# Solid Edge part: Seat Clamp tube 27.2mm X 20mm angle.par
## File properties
Last saved by: morva
Revision: 77
Accuracy: 0.990
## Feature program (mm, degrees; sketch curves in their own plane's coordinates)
sketch for "unnamed Protrusion 1" plane through (0.22, -6.8575, -2.251) normal (0, -1, 0) x-axis (0.94412, 0, 0.329602)
  line (-11.7005, 1.9664) -> (-10.7493, 1.6343)
  line (-10.7493, 1.6343) -> (-8.844, 0.9691)
  line (-9.4309, 5.4108) -> (-7.5256, 4.7456)
  line (-9.4309, 5.4108) -> (-10.3821, 5.7429)
extrude "unnamed Protrusion 1" add to key point along -normal
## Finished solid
Body 1: solid body, 6 faces, 12 edges, 8 vertices.
  Faces by surface: plane 4, cylinder 2
  Edges by curve: line 8, circle 4
Body 2: sheet body, 62 faces, 134 edges, 72 vertices.
  Faces by surface: cylinder 28, torus 20, plane 10, blend 4
  Edges by curve: circle 76, line 50, ellipse 8
Body 3: sheet body, 46 faces, 112 edges, 64 vertices.
  Faces by surface: cylinder 20, plane 14, torus 12
  Edges by curve: circle 50, line 44, intersection 12, ellipse 6
Body 4: sheet body, 19 faces, 49 edges, 28 vertices.
  Faces by surface: torus 10, cylinder 5, blend 4
  Edges by curve: circle 30, intersection 14, line 4, spline 1
Body 5: sheet body, 2 faces, 7 edges, 5 vertices.
  Faces by surface: spline 2
  Edges by curve: intersection 2, line 2, spline 2, curve on surface 1
Body 6: sheet body, 11 faces, 41 edges, 30 vertices.
  Faces by surface: plane 8, torus 2, cylinder 1
  Edges by curve: line 29, circle 12
Body 7: sheet body, 6 faces, 7 edges, 0 vertices.
  Faces by surface: cylinder 2, plane 2, torus 2
  Edges by curve: circle 7
Body 8: sheet body, 248 faces, 738 edges, 456 vertices.
  Faces by surface: cylinder 139, torus 47, blend 45, plane 14, spline 2, cone 1
  Edges by curve: circle 281, intersection 274, line 180, spline 3
Body 9: sheet body, 6 faces, 7 edges, 0 vertices.
  Faces by surface: cylinder 2, plane 2, torus 2
  Edges by curve: circle 7
Body 10: sheet body, 9 faces, 41 edges, 32 vertices.
  Faces by surface: plane 8, cylinder 1
  Edges by curve: line 32, circle 9
Bounding box of the edges (mm; curved faces can reach further): 54.955 x 52.830 x 66.815, from (-27.5476, -6.8575, -34.4784) to (27.4073, 45.9725, 32.3366).
Cylindrical faces by radius (mm): R0.1 x90, R0.25 x45, R0.5 x18, R1 x12, R1.5 x4, R2 x1, R2.2487 x1, R2.5 x2, R2.925 x1, R5 x5, R6.35 x4, R6.725 x1, R8 x5, R9 x1, R9.25 x3, R9.3 x1, R14 x1, R16 x1, R17 x1, R22.0001 x1, R26.5625 x1, R31.7259 x1
Conical faces (half-angle, radius in mm at the cone's reference point): 40.3645 deg R6.725 x1
Toroidal faces (ring radius, tube radius in mm): R0.5 r1 x8, R1.5 r0.5 x2, R3 r0.5 x4, R3.5 r1 x1, R4.35 r2 x8, R4.5 r0.5 x1, R5 r2 x2, R5.5 r0.5 x4, R6.225 r0.5 x1, R6.625 r0.1 x43, R6.825 r0.1 x1, R7 r1 x2, R7 r2.25 x2, R7.5 r0.5 x6, R8.5 r0.5 x2, R17 r1 x2, R21.0001 r1 x2, R27.0625 r0.5 x2, R31.2259 r0.5 x2
Planar faces by outward normal: +y 1, +z 1, -y 1, -z 1
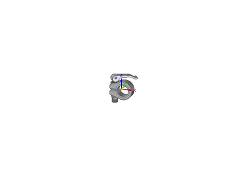
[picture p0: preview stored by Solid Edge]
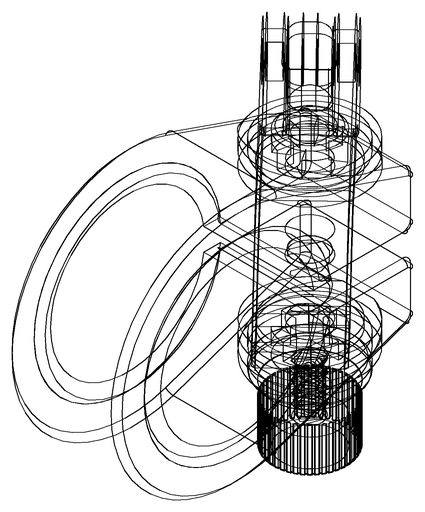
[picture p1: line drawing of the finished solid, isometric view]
